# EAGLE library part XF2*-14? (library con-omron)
OMRON FPC Connector Source : http://www.omron.com/ecb/products/pdf/fpc.pdf
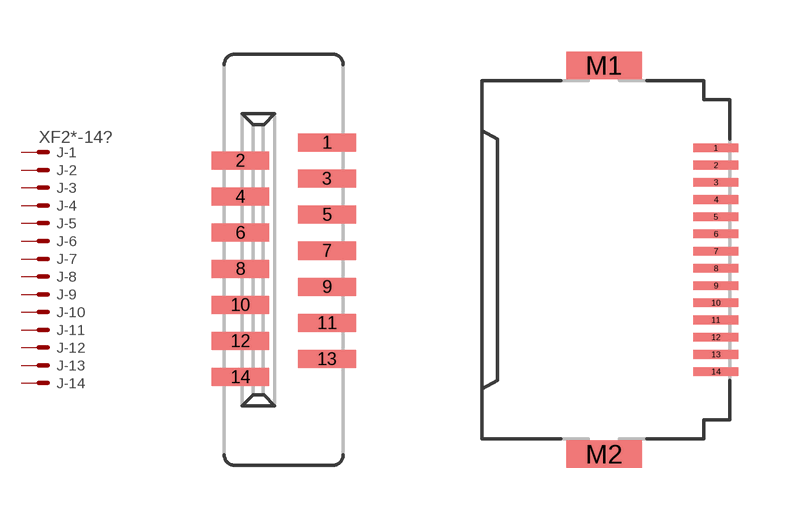
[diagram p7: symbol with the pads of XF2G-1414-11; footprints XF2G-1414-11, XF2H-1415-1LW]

Designator prefix J; gates -1=PV -2=P -3=P -4=P -5=P -6=P -7=P -8=P -9=P -10=P -11=P -12=P -13=P -14=P

## XF2G-1414-11 (MPN: XF2G-1414-11; OC_FARNELL: unknown; OC_NEWARK: 37M0758)  [XF2G-1414-11]
1  -1:MSV  pas
2  -2:MS  pas
3  -3:MS  pas
4  -4:MS  pas
5  -5:MS  pas
6  -6:MS  pas
7  -7:MS  pas
8  -8:MS  pas
9  -9:MS  pas
10  -10:MS  pas
11  -11:MS  pas
12  -12:MS  pas
13  -13:MS  pas
14  -14:MS  pas

## XF2H-1415-1LW (MF: OMRON COMPONENTS USA; MPN: XF2H-1415-1LW; OC_FARNELL: unknown; OC_NEWARK: 12J5137)  [XF2H-1415-1LW]
Pads as for XF2G-1414-11

## XF2J-1424-11 (MPN: XF2J-1424-11; OC_FARNELL: unknown; OC_NEWARK: 37M0824)  [XF2J-1424-11]
Pads as for XF2G-1414-11

## Footprint XF2G-1414-11 (pad centres in mm)
Non-ZIF Type (0.5 mm-pitch) Source : http://www.omron.com/ecb/products/pdf/fpc.pdf
smd 1.6 x 0.5: 1 1.2,3.25; 2 -1.2,2.75; 3 1.2,2.25; 4 -1.2,1.75; 5 1.2,1.25; 6 -1.2,0.75; 7 1.2,0.25; 8 -1.2,-0.25; 9 1.2,-0.75; 10 -1.2,-1.25; 11 1.2,-1.75; 12 -1.2,-2.25; 13 1.2,-2.75; 14 -1.2,-3.25

## Footprint XF2H-1415-1LW (pad centres in mm)
Standard Rotary Backlock Type (0.5 mm-pitch) Source : http://www.omron.com/ecb/products/pdf/fpc.pdf
smd 1.3 x 0.25: 1 3.175,3.25; 2 3.175,2.75; 3 3.175,2.25; 4 3.175,1.75; 5 3.175,1.25; 6 3.175,0.75; 7 3.175,0.25; 8 3.175,-0.25; 9 3.175,-0.75; 10 3.175,-1.25; 11 3.175,-1.75; 12 3.175,-2.25; 13 3.175,-2.75; 14 3.175,-3.25
smd 2.2 x 0.8: M1 -0.075,5.65; M2 -0.075,-5.65

## Footprint XF2J-1424-11 (pad centres in mm)
ZIF Slide-locking Type (0.5 mm-pitch) Standard Source : http://www.omron.com/ecb/products/pdf/fpc.pdf
smd 1.6 x 0.5: 1 1.2,3.25; 2 -1.2,2.75; 3 1.2,2.25; 4 -1.2,1.75; 5 1.2,1.25; 6 -1.2,0.75; 7 1.2,0.25; 8 -1.2,-0.25; 9 1.2,-0.75; 10 -1.2,-1.25; 11 1.2,-1.75; 12 -1.2,-2.25; 13 1.2,-2.75; 14 -1.2,-3.25
smd 2.9 x 1.4: M1 0,4.95; M2 0,-4.95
